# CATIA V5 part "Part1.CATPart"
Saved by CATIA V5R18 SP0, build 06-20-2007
Part number: Part1
Bounding box of the stored display mesh (mm): x 0 to 20, y -150 to 150, z -40 to 40
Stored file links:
  D:\Shriniwas\v5_r19\c16_CAT_v5r19\c16_Part\Slide curve Joint\Part1.CATPart
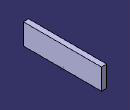
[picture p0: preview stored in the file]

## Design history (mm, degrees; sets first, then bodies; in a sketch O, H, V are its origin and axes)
Body1 (main body)
  Sketch1 on yz-plane, origin (0, 0, 0), H (0, 1, 0), V (0, 0, 1)
    line L1 (150, 40) -> (150, -40)
    line L2 (150, -40) -> (-150, -40)
    line L3 (-150, -40) -> (-150, 40)
    line L4 (-150, 40) -> (150, 40)
    length L4 = 300
    length L1 = 80
    vertical: L1 V, L3 V
    horizontal: L2 H, L4 H
    equidistance: L1 L3 O, L2 L4 O
  Pad1: profile Sketch1, direction (1, 0, 0), length 20
  Point1: type OnCurve, Support edge [face of Pad1 from Sketch1.L2 | end face of Pad1], Ratio 0.5
  Sketch2 on zx-plane, origin (0, 0, 0), H (-1, 0, 0), V (0, 0, 1)
    line L1 (-75, -185) -> (75, -185)
    point P1 (-75, -185)
    distance L1 H = 185
    length L1 = 150
    distance V P1 = 75
    horizontal: L1 H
